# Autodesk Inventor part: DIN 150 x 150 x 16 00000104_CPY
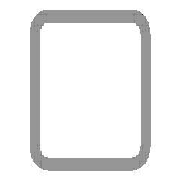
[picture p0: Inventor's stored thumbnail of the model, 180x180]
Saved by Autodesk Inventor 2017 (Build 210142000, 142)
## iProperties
Created: 2017-11
Part Number: DIN 150 x 150 x 16 00000104_CPY
Material: Steel, Mild
Description: Cold formed welded structural hollow sections of non-alloy and fine grain structural steel
Document SubType Name: Modeling
Standard: DIN
Designer: iusti
Standard Revision: 2006-07
Standards Organization: DIN
Language: en-US
Size Designation: 150 x 150 x 16
Categories: <MemberInstance><Categories><Category DisplayName="Structural Shapes" InternalName="089c4875-fa83-4c05-b084-43b9cc11f5ed" Mnemonic="GRDR"><CategoryParameter Dis
Stock Number: 150 x 150 x 16
Mass: 301820 g
Surface Area: 48238.1 cm^2
Volume: 38448.4 cm^3
Density: 7.85 g/cm^3
Appearance: Semi-Polished
IsCustomPart: 1
G_W: 150.000 mm
G_H: 150.000 mm
G_L: 5233.011 mm
+29768780-A419-4CF3-9340-1BC278E7B28F+CUTDETAIL2: Cut
+346FD258-9F9C-4BDE-884E-4FE9BE76FCEA+CUTDETAIL3: Miter 69.88 deg
_CCFamilyMember: 76
_CCFamilyDisplayName: DIN EN 10219-2 (Square Hollow Section - Cold Formed) - Cold formed welded structural hollow sections of non-alloy and fine grain structural steel
_FrameMemberDoc: Frame Member File
_Version: 15.0.0
_GetPNFromCC: 1
Author: iusti
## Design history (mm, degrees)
node "Start plane"
node "End plane"
sketch "Sketch"
  geometry: L1 (-75, -27)-(-75, 27); L2 (-27, 75)-(27, 75); L3 (75, 27)-(75, -27); L4 (27, -75)-(-27, -75); L5 (-27, 59)-(27, 59); L6 (59, 27)-(59, -27); L7 (27, -59)-(-27, -59); L8 (-59, -27)-(-59, 27); L9 (0, 118.918)-(0, -118.918) reference; L10 (-118.918, 0)-(118.918, 0) reference; A1 r 48 centre (-27, -27) between (-75, -27) and (-27, -75); A2 r 48 centre (-27, 27) between (-27, 75) and (-75, 27); A3 r 48 centre (27, 27) between (75, 27) and (27, 75); A4 r 48 centre (27, -27) between (27, -75) and (75, -27); A5 r 32 centre (-27, 27) between (-27, 59) and (-59, 27); A6 r 32 centre (27, 27) between (59, 27) and (27, 59); A7 r 32 centre (27, -27) between (27, -59) and (59, -27); A8 r 32 centre (-27, -27) between (-59, -27) and (-27, -59)
  constraints: 16 end point, 16 point on circle, 8 centre point, 8 tangent, 4 parallel, 3 equal radius, 2 perpendicular, 7 other
  dimensions: "d7" = 48 radius of A1 (= G_IR); "d10" = 150 distance between parallel lines of L2 L4 (= G_H); "d11" = 150 distance between parallel lines of L1 L3 (= G_W); "d12" = 16 distance between parallel lines of L3 L6 (= G_T); "d15" = 75 distance between parallel lines of L2 L10 (= 0.5 x d10); "d16" = 75 distance between parallel lines of L9 L3 (= 0.5 x d11)
extrude "Body" new body sketch "Sketch" stored distance "d3" = 5233.01077 (= G_L); taper "d4" = 0 deg
node "Driven Length"
  sketch "Sketch3"
    geometry: L1 (0, 0)-(10, 0) reference
    constraints: 2 end point, 1 horizontal
  workplane "Work Plane3"
  sketch "Sketch4"
    geometry: L1 (-2, 34.78)-(12, 34.78) reference; L2 (-2, 5267.791)-(12, 5267.791) reference
    dimensions: "d18" = 5233.01077 distance between parallel lines of L1 L2 (derived)
workplane "Work Plane5"
split "Split2"
workplane "Work Plane6"
split "Split3"
body "Solid1"
other parameters: "G_W" = 150 [user parameter; used in 1 equation term], "G_H" = 150 [user parameter; used in 1 equation term], "G_T" = 16 [user parameter; used in 1 equation term], "G_IR" = 48 [user parameter; used in 1 equation term], "G_L" = 5233.01077 (= d18) [user parameter; used in 1 equation term], "G_OFFSET_START" = -34.77977 [user parameter; used in 1 equation term], "G_OFFSET_END" = 27.4779 [user parameter; used in 1 equation term], "d13" = 34.77977 (= -G_OFFSET_START), "d14" = 5267.79054 (= G_OFFSET_END + B_L), "B_L" = 5240.31264 [user parameter; used in 1 equation term], "d17" = 90 deg
